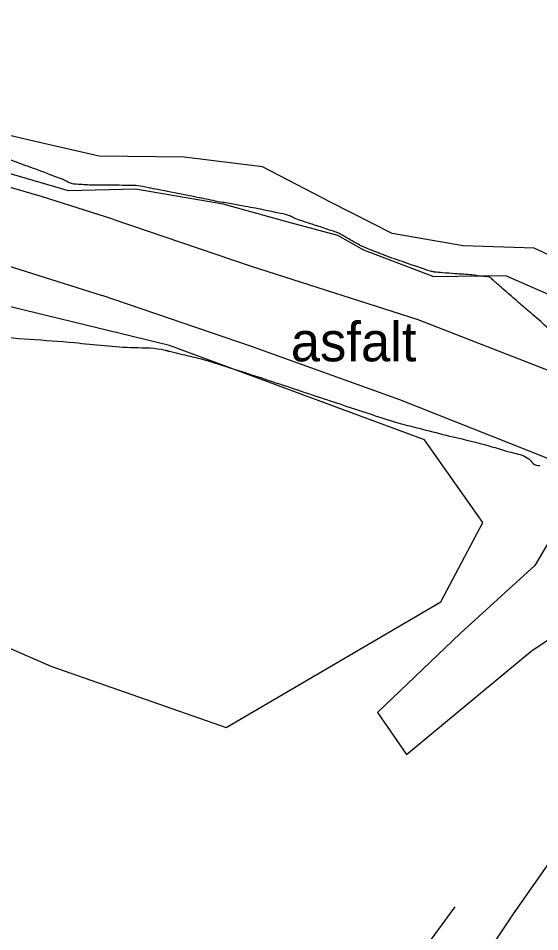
# Model space of a CAD drawing. Extents: x -475575 to -473225, y -1116053 to -1114104.
# Drawn here: x -473885.6 to -473865.72, y -1115632.73 to -1115597.89 of the extents above; entities that cross this region are included whole.
import ezdxf

# ---------------------------------------------------------------- set-up
doc = ezdxf.new("R2010")
doc.units = 0
doc.layers.add('Vrstevnice_vedlejsi', color=7, linetype='Continuous')
doc.layers.add('Vrstva_10', color=7, linetype='Continuous')

msp = doc.modelspace()

# ---------------------------------------------------------------- linework, layer by layer
at = {"layer": 'Vrstevnice_vedlejsi'}
for points in [[(-473855.17399999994, -1115614.6049999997), (-473856.7409999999, -1115613.8519999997), (-473857.93899999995, -1115613.3399999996), (-473858.7689999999, -1115613.0669999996), (-473859.2299999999, -1115613.0349999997), (-473859.5999999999, -1115613.0109999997), (-473859.8789999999, -1115612.9969999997), (-473860.06599999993, -1115612.9919999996), (-473860.6559999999, -1115612.7599999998), (-473861.6499999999, -1115612.3019999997), (-473863.0469999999, -1115611.6169999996), (-473864.02599999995, -1115611.0749999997), (-473864.5889999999, -1115610.6769999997), (-473864.73399999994, -1115610.4209999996), (-473865.0249999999, -1115610.0809999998), (-473865.46299999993, -1115609.6549999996), (-473866.04799999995, -1115609.1429999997), (-473866.52699999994, -1115608.7239999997), (-473866.90199999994, -1115608.3979999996), (-473867.1719999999, -1115608.1639999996), (-473867.37499999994, -1115607.9859999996), (-473867.51099999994, -1115607.8619999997), (-473867.5789999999, -1115607.7939999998), (-473867.84199999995, -1115607.7329999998), (-473868.29899999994, -1115607.6799999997), (-473868.94999999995, -1115607.6349999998), (-473869.42499999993, -1115607.5969999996), (-473869.72299999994, -1115607.5669999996), (-473869.8439999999, -1115607.5429999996), (-473870.18899999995, -1115607.4349999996), (-473870.75599999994, -1115607.2399999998), (-473871.5469999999, -1115606.9609999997), (-473872.17399999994, -1115606.7169999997), (-473872.63999999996, -1115606.5079999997), (-473872.9419999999, -1115606.3349999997), (-473873.1649999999, -1115606.2079999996), (-473873.30899999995, -1115606.1259999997), (-473873.3729999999, -1115606.0899999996), (-473873.58599999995, -1115606.0119999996), (-473873.9479999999, -1115605.8909999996), (-473874.4579999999, -1115605.7269999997), (-473874.8439999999, -1115605.5959999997), (-473875.1049999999, -1115605.4969999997), (-473875.2429999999, -1115605.4299999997), (-473875.5949999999, -1115605.3359999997), (-473876.16199999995, -1115605.2149999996), (-473876.94499999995, -1115605.0669999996), (-473877.47799999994, -1115604.9679999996), (-473877.76199999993, -1115604.9169999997), (-473877.7969999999, -1115604.9159999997), (-473878.1669999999, -1115604.8449999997), (-473878.86999999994, -1115604.7039999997), (-473879.90799999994, -1115604.4939999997), (-473880.6379999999, -1115604.3509999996), (-473881.05899999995, -1115604.2759999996), (-473881.1719999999, -1115604.2689999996), (-473881.4919999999, -1115604.2629999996), (-473882.0199999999, -1115604.2579999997), (-473882.75599999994, -1115604.2549999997), (-473883.29899999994, -1115604.2239999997), (-473883.6489999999, -1115604.1679999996), (-473883.8059999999, -1115604.0849999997), (-473884.16799999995, -1115603.9359999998), (-473884.73399999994, -1115603.7209999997), (-473885.5039999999, -1115603.4399999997), (-473886.13699999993, -1115603.1969999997), (-473886.63099999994, -1115602.9929999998), (-473886.98799999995, -1115602.8269999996), (-473887.3599999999, -1115602.6749999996), (-473887.7459999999, -1115602.5349999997), (-473888.14699999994, -1115602.4089999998), (-473888.61999999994, -1115602.2889999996), (-473889.1659999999, -1115602.1739999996), (-473889.78299999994, -1115602.0649999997), (-473890.36399999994, -1115601.9219999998), (-473890.90699999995, -1115601.7469999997), (-473891.41299999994, -1115601.5379999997), (-473892.0199999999, -1115601.3039999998), (-473892.72699999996, -1115601.0449999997), (-473893.5359999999, -1115600.7609999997), (-473894.1819999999, -1115600.5179999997), (-473894.6669999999, -1115600.3149999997), (-473894.9909999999, -1115600.1509999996), (-473895.49999999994, -1115599.8899999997), (-473896.1939999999, -1115599.5299999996), (-473897.07499999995, -1115599.0729999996), (-473897.7149999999, -1115598.7439999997), (-473898.11399999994, -1115598.5449999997), (-473898.2729999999, -1115598.4749999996), (-473898.5579999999, -1115598.3129999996), (-473898.9689999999, -1115598.0579999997), (-473899.50599999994, -1115597.7099999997), (-473899.78899999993, -1115597.0789999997), (-473899.8189999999, -1115596.1629999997), (-473899.5949999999, -1115594.9629999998), (-473899.27699999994, -1115593.2229999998), (-473898.86299999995, -1115590.9409999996)], [(-473918.5273500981, -1115615.8243041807), (-473918.52699999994, -1115615.8239999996), (-473916.9219999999, -1115614.6449999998), (-473915.1319999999, -1115613.7259999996), (-473912.9689999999, -1115612.6879999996), (-473910.4329999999, -1115611.5309999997), (-473907.5249999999, -1115610.2549999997), (-473905.5559999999, -1115609.3779999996), (-473904.52599999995, -1115608.9019999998), (-473904.43499999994, -1115608.8249999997), (-473904.3679999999, -1115608.7679999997), (-473904.3239999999, -1115608.7289999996), (-473904.30499999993, -1115608.7089999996), (-473903.53199999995, -1115608.5079999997), (-473902.0069999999, -1115608.1269999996), (-473899.72899999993, -1115607.5659999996), (-473897.9869999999, -1115607.2669999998), (-473896.7809999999, -1115607.2309999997), (-473896.1119999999, -1115607.4579999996), (-473895.51599999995, -1115607.6209999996), (-473894.9919999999, -1115607.7209999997), (-473894.5419999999, -1115607.7559999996), (-473894.04299999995, -1115607.8419999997), (-473893.49399999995, -1115607.9779999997), (-473892.89699999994, -1115608.1649999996), (-473892.2739999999, -1115608.4409999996), (-473891.62599999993, -1115608.8049999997), (-473890.9529999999, -1115609.2579999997), (-473889.3669999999, -1115609.6519999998), (-473886.86899999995, -1115609.9859999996), (-473883.4589999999, -1115610.2609999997), (-473881.1709999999, -1115610.4479999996), (-473880.0029999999, -1115610.5469999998), (-473879.95699999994, -1115610.5589999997), (-473879.91399999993, -1115610.5699999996), (-473879.87499999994, -1115610.5799999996), (-473879.83799999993, -1115610.5889999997), (-473879.6279999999, -1115610.6389999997), (-473879.2429999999, -1115610.7329999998), (-473878.6829999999, -1115610.8679999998), (-473877.5739999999, -1115611.2049999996), (-473875.91399999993, -1115611.7429999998), (-473873.7029999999, -1115612.4829999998), (-473872.1069999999, -1115613.0089999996), (-473871.12399999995, -1115613.3209999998), (-473870.75599999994, -1115613.4189999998), (-473870.05499999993, -1115613.5969999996), (-473869.02099999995, -1115613.8559999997), (-473867.6549999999, -1115614.1959999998), (-473866.6929999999, -1115614.4759999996), (-473866.13499999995, -1115614.6959999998), (-473865.9809999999, -1115614.8559999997), (-473865.8409999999, -1115614.9419999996), (-473865.7159999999, -1115614.9519999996)], [(-473861.82699999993, -1115633.5539999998), (-473861.5829999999, -1115633.2829999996), (-473861.3189999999, -1115632.9449999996), (-473861.0339999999, -1115632.5399999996), (-473860.72799999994, -1115632.0659999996), (-473860.45599999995, -1115631.6379999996), (-473860.21699999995, -1115631.2569999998), (-473860.01099999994, -1115630.9199999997), (-473859.78199999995, -1115630.5799999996), (-473859.53199999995, -1115630.2339999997), (-473859.2589999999, -1115629.8839999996), (-473858.8989999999, -1115629.5449999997), (-473858.45099999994, -1115629.2159999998), (-473857.9149999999, -1115628.8979999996), (-473857.50499999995, -1115628.6529999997), (-473857.2189999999, -1115628.4809999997), (-473857.0579999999, -1115628.3819999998), (-473856.8659999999, -1115628.2499999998), (-473856.6439999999, -1115628.0849999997), (-473856.38999999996, -1115627.8869999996), (-473856.0189999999, -1115627.5459999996), (-473855.5299999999, -1115627.0609999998), (-473854.92299999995, -1115626.4329999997), (-473854.42299999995, -1115625.9109999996), (-473854.03199999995, -1115625.4949999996), (-473853.7479999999, -1115625.1849999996), (-473853.47299999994, -1115624.8339999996), (-473853.2089999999, -1115624.4409999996), (-473852.9539999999, -1115624.0069999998), (-473852.79399999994, -1115623.6419999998), (-473852.7299999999, -1115623.3469999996), (-473852.76099999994, -1115623.1209999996), (-473852.82699999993, -1115622.9169999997), (-473852.9309999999, -1115622.7369999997), (-473853.06999999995, -1115622.5789999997), (-473853.2139999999, -1115622.4499999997), (-473853.36299999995, -1115622.3479999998), (-473853.51699999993, -1115622.2749999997), (-473853.79799999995, -1115622.2999999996), (-473854.20599999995, -1115622.4249999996), (-473854.7419999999, -1115622.6479999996), (-473855.1499999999, -1115622.8069999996), (-473855.42999999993, -1115622.9019999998), (-473855.5839999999, -1115622.9329999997), (-473855.7209999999, -1115622.9899999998), (-473855.8399999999, -1115623.0729999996), (-473855.9429999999, -1115623.1819999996), (-473856.1989999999, -1115623.5059999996), (-473856.60799999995, -1115624.0469999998), (-473857.1699999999, -1115624.8029999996), (-473857.7049999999, -1115625.4599999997), (-473858.21299999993, -1115626.0199999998), (-473858.6939999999, -1115626.4809999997), (-473859.07599999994, -1115626.8359999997), (-473859.3609999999, -1115627.0859999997), (-473859.5469999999, -1115627.2289999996), (-473859.8789999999, -1115627.5499999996), (-473860.3559999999, -1115628.0469999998), (-473860.9799999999, -1115628.7209999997), (-473861.4329999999, -1115629.2189999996), (-473861.7149999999, -1115629.5409999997), (-473861.82699999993, -1115629.6879999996), (-473862.09299999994, -1115629.9729999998), (-473862.5129999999, -1115630.3949999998), (-473863.08699999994, -1115630.9559999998), (-473863.5239999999, -1115631.3989999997), (-473863.8239999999, -1115631.7259999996), (-473863.98799999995, -1115631.9349999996), (-473864.19999999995, -1115632.2409999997), (-473864.4589999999, -1115632.6439999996), (-473864.76599999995, -1115633.1439999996), (-473865.0309999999, -1115633.5449999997), (-473865.2519999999, -1115633.8449999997), (-473865.4309999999, -1115634.0459999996), (-473865.73299999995, -1115634.4129999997), (-473866.15699999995, -1115634.9469999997), (-473866.7049999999, -1115635.6469999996), (-473867.15199999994, -1115636.2019999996), (-473867.49999999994, -1115636.6089999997), (-473867.7479999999, -1115636.8709999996), (-473868.2369999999, -1115637.3689999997), (-473868.96699999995, -1115638.1049999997), (-473869.9379999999, -1115639.0779999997), (-473870.6859999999, -1115639.8359999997), (-473871.21199999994, -1115640.3809999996), (-473871.51499999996, -1115640.7119999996), (-473871.77599999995, -1115641.0309999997), (-473871.99399999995, -1115641.3389999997), (-473872.1699999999, -1115641.6349999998), (-473872.34699999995, -1115641.9479999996), (-473872.5239999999, -1115642.2759999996), (-473872.7029999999, -1115642.6209999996), (-473872.88599999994, -1115642.9669999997), (-473873.0739999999, -1115643.3129999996), (-473873.26599999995, -1115643.6609999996), (-473873.52699999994, -1115643.9809999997), (-473873.8549999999, -1115644.2709999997)]]:
    msp.add_spline(points, degree=3, dxfattribs=at)
at = {"layer": 'Vrstva_10'}
for points in [[(-473851.7469999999, -1115613.5229999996), (-473853.32099999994, -1115611.846), (-473856.7309999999, -1115610.434), (-473860.0849999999, -1115609.157), (-473862.94099999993, -1115608.0439999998), (-473865.9269999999, -1115606.6549999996), (-473868.63999999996, -1115606.5709999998), (-473871.3439999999, -1115606.096), (-473873.69099999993, -1115604.8989999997), (-473876.28799999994, -1115603.5489999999), (-473879.2729999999, -1115603.1909999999), (-473882.50999999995, -1115603.1539999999), (-473884.7909999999, -1115602.6309999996), (-473887.5199999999, -1115601.9949999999), (-473890.5799999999, -1115601.353), (-473894.36999999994, -1115600.1289999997), (-473897.94599999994, -1115598.4579999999), (-473901.11499999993, -1115596.8019999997), (-473904.70699999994, -1115595.0219999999), (-473906.1379999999, -1115594.3739999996)], [(-473881.9968808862, -1115605.5562530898), (-473884.67399999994, -1115604.6969999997), (-473890.76699999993, -1115602.9299999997), (-473894.4329999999, -1115601.6249999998), (-473898.28299999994, -1115600.0539999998), (-473902.0729999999, -1115598.4859999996), (-473904.4259999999, -1115597.2059999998), (-473906.37499999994, -1115596.2429999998), (-473908.14599999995, -1115595.1209999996)], [(-473912.21699999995, -1115596.1759999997), (-473909.19599999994, -1115597.9229999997), (-473905.2249999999, -1115599.7869999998), (-473902.27199999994, -1115601.3039999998), (-473898.5399999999, -1115603.0389999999), (-473894.0089999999, -1115604.8709999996), (-473888.97699999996, -1115606.3929999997), (-473883.36999999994, -1115608.1619999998), (-473882.3948296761, -1115608.4635301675)], [(-473852.79399999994, -1115613.9734999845), (-473853.8889999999, -1115613.6159999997), (-473855.54999999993, -1115612.5799999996), (-473858.4969999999, -1115611.4929999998), (-473861.75599999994, -1115610.1089999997), (-473864.1649999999, -1115608.9599999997), (-473867.0139999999, -1115607.7189999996), (-473869.7479999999, -1115607.7449999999), (-473872.42499999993, -1115606.7329999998), (-473873.41299999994, -1115606.1679999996), (-473875.2149999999, -1115605.6919999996), (-473877.7839999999, -1115604.9729999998), (-473881.1289999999, -1115604.4019999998), (-473883.68399999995, -1115604.4659999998), (-473887.13499999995, -1115603.4639999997), (-473890.16899999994, -1115602.738), (-473894.2839999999, -1115601.2859999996), (-473898.0129999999, -1115599.5849999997), (-473901.5789999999, -1115598.0669999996), (-473904.5349999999, -1115596.7199999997)], [(-473881.9968808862, -1115605.5562530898), (-473876.7519999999, -1115607.3339999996), (-473870.3659999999, -1115609.3789999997), (-473865.5289999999, -1115611.2639999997), (-473860.0249999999, -1115613.4239999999), (-473852.8119999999, -1115616.4949999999), (-473845.7689999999, -1115619.3969999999), (-473840.1059999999, -1115621.7299999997)], [(-473840.17999999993, -1115626.1729999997), (-473843.6099999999, -1115624.1689999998), (-473848.0089999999, -1115621.8889999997), (-473853.00099999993, -1115619.755), (-473858.3599999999, -1115617.7129999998), (-473863.9799999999, -1115615.5039999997), (-473865.4749999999, -1115614.6549999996), (-473871.04799999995, -1115612.4489999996), (-473876.70599999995, -1115610.4029999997), (-473882.3948296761, -1115608.4635301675)], [(-473863.9799999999, -1115615.5039999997), (-473865.90799999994, -1115618.7679999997), (-473868.74999999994, -1115621.3579999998), (-473871.90299999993, -1115624.3659999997), (-473870.7949999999, -1115625.9729999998), (-473866.04799999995, -1115622.0339999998), (-473862.3769999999, -1115619.5739999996), (-473859.3599999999, -1115618.1059999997), (-473858.3599999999, -1115617.7129999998)], [(-473868.57499999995, -1115634.8329999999), (-473866.7159999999, -1115632.0529999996), (-473864.39099999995, -1115628.7389999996), (-473862.62599999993, -1115626.4229999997), (-473859.80499999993, -1115623.5159999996), (-473858.0849999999, -1115621.3319999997), (-473857.12999999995, -1115619.63)], [(-473868.956, -1115631.7839999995), (-473875.7950000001, -1115641.1259999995), (-473881.1119999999, -1115647.6849999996)]]:
    msp.add_lwpolyline(points, dxfattribs=at)
msp.add_lwpolyline([(-473896.62549998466, -1115610.0069999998), (-473898.1919999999, -1115613.5609999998), (-473896.3289999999, -1115616.3269999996), (-473891.53299999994, -1115619.4799999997), (-473884.36299999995, -1115622.6079999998), (-473877.6719999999, -1115624.9479999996), (-473869.4874999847, -1115620.1499999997), (-473867.88499999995, -1115617.1289999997), (-473870.10399999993, -1115613.9739999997), (-473879.83599999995, -1115610.3689999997), (-473890.0449999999, -1115607.8859999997), (-473894.1179999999, -1115608.728)], close=True, dxfattribs=at)

# ---------------------------------------------------------------- texts
msp.add_text('asfalt', height=1.5, dxfattribs=at).set_placement((-473875.20874044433, -1115610.9740878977))

doc.saveas('drawing.dxf')
